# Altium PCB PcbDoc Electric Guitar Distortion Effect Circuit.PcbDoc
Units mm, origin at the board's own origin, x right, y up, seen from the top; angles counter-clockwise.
Board outline 141.4 x 38.35 mm, 2 copper layers (Top Layer, Bottom Layer), stack 1.534 mm thick; 31 components, 18 nets, 78 pads, 0 vias.
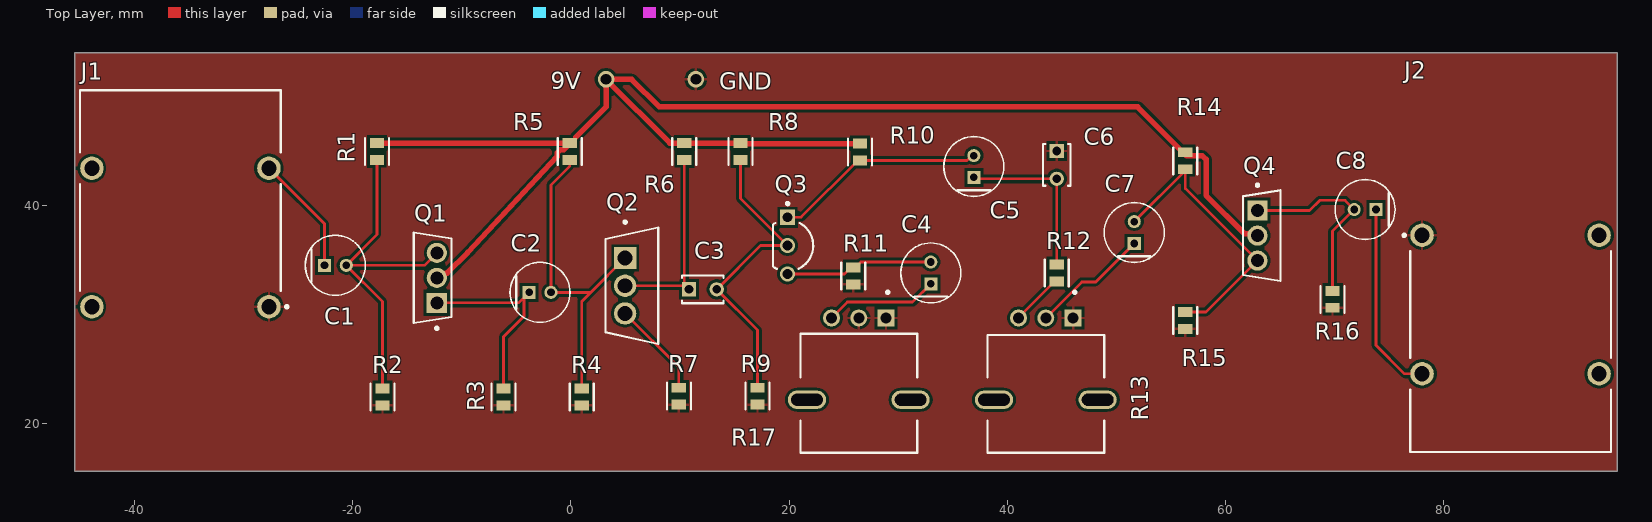
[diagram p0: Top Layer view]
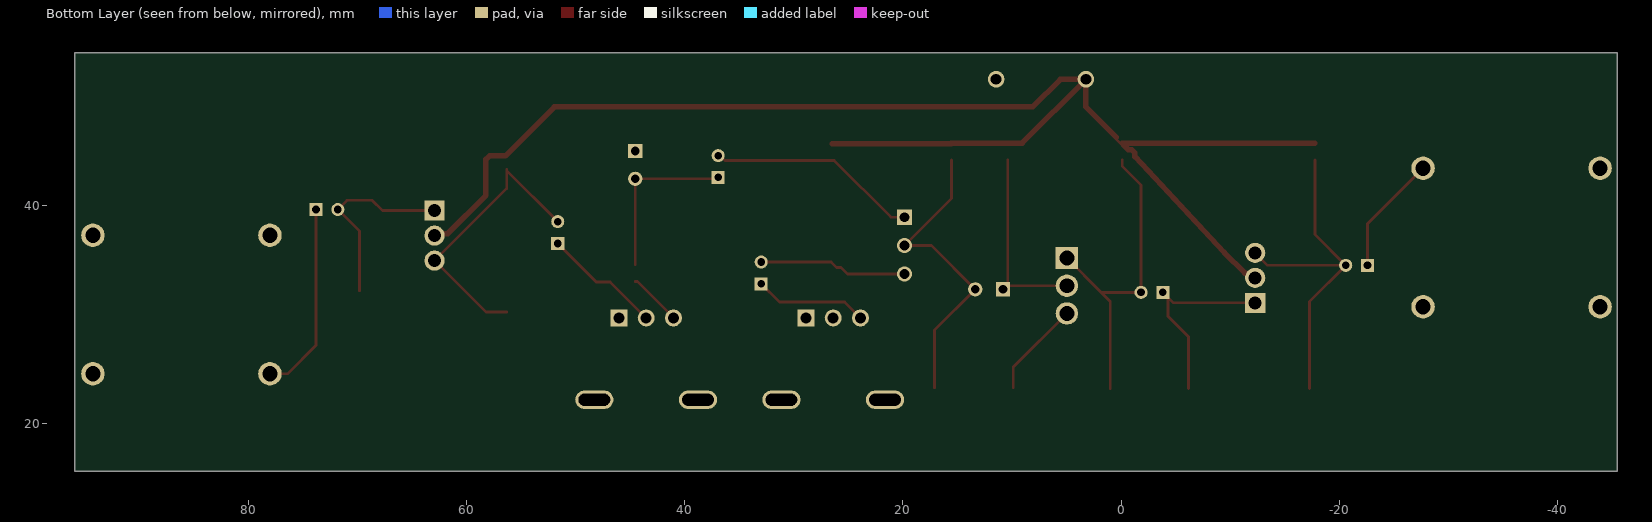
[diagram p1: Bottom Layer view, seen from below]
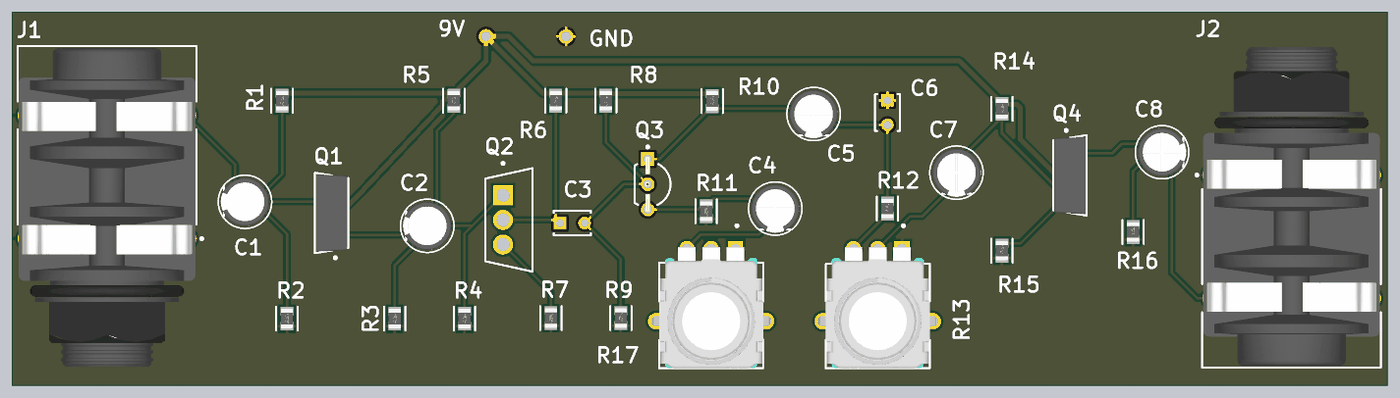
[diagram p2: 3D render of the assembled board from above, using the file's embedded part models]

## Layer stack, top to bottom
Top Solder: solder mask 0.0127, Solder Resist, Dk 3.3
Top Layer: signal copper 0.0178
Dielectric1: core 1.4986, FR-4, Dk 4.3
Bottom Layer: signal copper 0.0178
Bottom Solder: solder mask 0.0127, Solder Resist, Dk 3.3

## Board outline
-45.482,15.672 -45.482,54.026 95.917,54.026 95.917,15.672

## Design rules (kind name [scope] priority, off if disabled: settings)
Clearance [All] p1: gap=0.254 ignorepadtopadclearanceinfootprint=FALSE
DiffPairsRouting [All] p1: maxlimit=0.254 minlimit=0.254 mostfreqgap=0.254 toplayer_minwidth=0.254 toplayer_maxwidth=0.254 toplayer_prefwidth=0.254 bottomlayer_minwidth=0.254 bottomlayer_maxwidth=0.254 bottomlayer_prefwidth=0.254 maxuncoupledlength=12.7
HoleSize [All] p1: absolutevalues=TRUE maxlimit=7.62 minlimit=0.254 maxpercent=80.000 minpercent=20.000
MinimumAnnularRing [All] p1: minimumring=0.2
PasteMaskExpansion [All] p1: expansion=0.254
PlaneClearance [All] p1: clearance=0.381
PlaneConnect [All] p1: pad.planeconnectstyle=Relief pad.reliefexpansion=0.508 pad.reliefentries=4 pad.reliefconductorwidth=0.254 pad.reliefairgap=0.254 via.planeconnectstyle=Direct via.reliefexpansion=0.508 via.reliefentries=4 via.reliefconductorwidth=0.254 via.reliefairgap=0.254
PolygonConnect [All] p1: thpad.connectstyle=Relief thpad.reliefconductorwidth=0.254 thpad.reliefentries=4 thpad.polygonreliefangle="90 Angle" thpad.airgapwidth=0.254 smdpad.connectstyle=Relief smdpad.reliefconductorwidth=0.254 smdpad.reliefentries=4 smdpad.polygonreliefangle="90 Angle" smdpad.airgapwidth=0.254 via.connectstyle=Direct via.reliefconductorwidth=0.254 via.reliefentries=4 via.polygonreliefangle="90 Angle" via.airgapwidth=0.254
RoutingVias [All] p1: holewidth=0.254 width=0.508 viastyle="Through Hole" minholewidth=0.254 minwidth=0.508 maxholewidth=0.254 maxwidth=0.508
SMDNeckDown [All] p1: percent=100.000
SilkToSolderMaskClearance SilkscreenOverComponentPads [IsPad] p1: minsilkscreentomaskgap=0.254 clearancetoexposedcopper=TRUE
SolderMaskExpansion [All] p1: expansion=0.254 istentingtop=FALSE
SupplyNets "Schematic Supply Nets_1" [InNet('9V')] p1: voltage=0.000
SupplyNets "Schematic Supply Nets" [InNet('GND')] p2: voltage=0.000
Width [All] p1: maxlimit=1 minlimit=0.254 preferedwidth=0.254 bottomlayer_maxwidth=0.254 minimp=50.000000 maximp=50.000000 favimp=50.000000
24 further rules are at their usual default settings.

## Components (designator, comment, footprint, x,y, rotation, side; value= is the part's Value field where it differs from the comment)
C1 "1uF" FP-RAD-TH-D_5_0_5-L_11_1-MFG -21.587,34.535 r0 top
C2 "1uF" FP-RAD-TH-D_5_0_5-L_11_1-MFG -2.827,32.055 r0 top
C3 "10nF" KEMT-C315-THT-2 12.098,32.335 r0 top
C4 "10uF" FP-RAD-TH-D_5_0_5-L_11_1-MFG 32.991,33.838 r90 top
C5 "1uF" FP-RAD-TH-D_5_0_5-L_11_1-MFG 36.935,43.592 r90 top
C6 "10nF" KEMT-C315-THT-2 44.535,43.737 r270 top
C7 "1uF" FP-RAD-TH-D_5_0_5-L_11_1-MFG 51.638,37.541 r90 top
C8 "4.7uF" FP-RAD-TH-D_5_0_5-L_11_1-MFG 72.796,39.649 r180 top
J1 "NMJ4HFD2" FP-NMJ4HFD2-MFG -35.789,33.96 r270 top
J2 "NMJ4HFD2" FP-NMJ4HFD2-MFG 86.131,34.061 r90 top
Q1 "BD175" FP-340AS-MFG -12.675,33.385 r180 top
Q2 "IRFZ44N" FP-TO-220AB-MFG 5.588,32.664 r0 top
Q3 "BC337-40RL1G" ONSC-TO-92-3-29-11_AM_BL 19.862,36.347 r270 top
Q4 "BD175" FP-340AS-MFG 63.322,37.262 r0 top
R1 "470k" FP-CRGP0805-IPC_C -17.772,44.96 r90 top value=470KΩ
R2 "470k" FP-CRGP0805-IPC_C -17.272,22.479 r90 top value=470KΩ
R3 "1K" FP-CRGP0805-IPC_C -6.177,22.479 r90 top value=470KΩ
R4 "100k" FP-CRGP0805-IPC_C 1.004,22.479 r90 top value=470KΩ
R5 "120K" FP-CRGP0805-IPC_C -0.096,44.96 r90 top value=470KΩ
R6 "15k" FP-CRGP0805-IPC_C 10.398,44.96 r90 top value=470KΩ
R7 "1K" FP-CRGP0805-IPC_C 9.898,22.538 r90 top value=470KΩ
R8 "47k" FP-CRGP0805-IPC_C 15.551,44.96 r90 top value=470KΩ
R9 "27k" FP-CRGP0805-IPC_C 17.1,22.538 r90 top value=470KΩ
R10 "6.8k" FP-CRGP0805-IPC_C 26.502,44.922 r90 top value=470KΩ
R11 "4.7k" FP-CRGP0805-IPC_C 25.877,33.564 r90 top value=470KΩ
R12 "100k" FP-CRGP0805-IPC_C 44.535,33.838 r90 top value=470KΩ
R13 "10k" FP-RK09L1140A2U-MFG 43.535,23.038 r180 top value=10kΩ
R14 "1M" FP-CRGP0805-IPC_C 56.319,44.12 r90 top value=470KΩ
R15 "1M" FP-CRGP0805-IPC_C 56.319,29.489 r90 top value=470KΩ
R16 "1K" FP-CRGP0805-IPC_C 69.819,31.42 r90 top value=470KΩ
R17 "10k" FP-RK09L1140A2U-MFG 26.391,23.038 r180 top value=10kΩ

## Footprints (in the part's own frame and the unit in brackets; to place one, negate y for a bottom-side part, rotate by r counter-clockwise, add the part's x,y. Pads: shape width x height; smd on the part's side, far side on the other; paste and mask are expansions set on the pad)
FP-340AS-MFG [mm]
  rect 1.85x1.85 hole 1.2 paste-2539.97 mask+0: 1(-0.387,2.29)
  round 1.85 hole 1.2 paste-2539.97 mask+0: 2(-0.387,0) 3(-0.387,-2.29)
  silkscreen extent -1.73,-4.15 1.73,4.75, body extent -1.83,-4.25 1.83,4.25, height 0.25
FP-CRGP0805-IPC_C [mm]
  rect 0.906x1.31 smd paste+0 mask+0: 1(-0.776,0) 2(0.776,0)
  silkscreen extent -1.23,-1.1 1.23,1.1, body extent -1.33,-0.8 1.33,0.8, height 0.25
FP-NMJ4HFD2-MFG [mm]
  round 2.15 hole 1.4 paste-2539.97 mask+0: S(3.225,8.115) SN(3.225,-8.115) T(-9.475,8.115) TN(-9.475,-8.115)
  silkscreen extent -16.63,-9.2 3.35,9.88, body extent -16.73,-9.3 16.73,9.3, height 0.25
FP-RAD-TH-D_5_0_5-L_11_1-MFG [mm]
  rect 1.2x1.2 hole 0.7 paste-2539.97 mask+0: 1(-1,0)
  round 1.2 hole 0.7 paste-2539.97 mask+0: 2(1,0)
  silkscreen extent -2.75,-2.75 2.75,2.75, body extent -2.85,-2.85 2.85,2.85, height 0.25
FP-RK09L1140A2U-MFG [mm]
  rect 1.55x1.55 hole 1 paste-2539.97 mask+0: 1(-2.5,-6.675)
  round 1.55 hole 1 paste-2539.97 mask+0: 2(0,-6.675) 3(2.5,-6.675)
  rrect100% 3.5x1.7 hole 1.1 slot 2.9 at 0 deg paste-2539.97 mask+0: 4(-4.75,0.825) 5(4.75,0.825)
  silkscreen extent -5.35,-9.15 5.35,5.68, body extent -6.6,-7.55 6.6,5.77, height 0.25
FP-TO-220AB-MFG [mm]
  rect 2.05x2.05 hole 1.35 paste-2539.97 mask+0: 1(-0.62,2.54)
  round 2.05 hole 1.35 paste-2539.97 mask+0: 2(-0.62,0) 3(-0.62,-2.54)
  silkscreen extent -2.41,-5.34 2.41,5.96
KEMT-C315-THT-2 [mm] "THD, 2-Leads, Body 3.81x2.54mm"
  rect 1.3x1.3 hole 0.8: 1(-1.27,0)
  round 1.3 hole 0.8: 2(1.27,0)
  silkscreen extent -1.91,-1.27 1.91,1.27, body extent -1.91,-1.27 1.91,1.27, height 4.66
ONSC-TO-92-3-29-11_AM_BL [mm] "TO, 3-Leads, Body Dia 4.7mm, Pitch 2.6mm"
  rect 1.4x1.4 hole 0.9: 1(-2.6,0)
  round 1.4 hole 0.9: 2(0,0) 3(2.6,0)
  silkscreen extent -3.97,-1.34 2.13,2.35, body extent -2.84,-1.34 2.84,2.35, height 5.33

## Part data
C1 C2 C5 C7: library part CMP-05427-001266-1, "Aluminum Electrolytic Capacitors (Radial Lead Type) 1uF ±20% 50V", Case/Package=Radial, Max Operating Temperature=105°C, Min Operating Temperature=-40°C, Package Quantity=2000, Ripple Current=8mA, Tolerance=20%, Voltage Rating=50V
C3 C6: library part CMP-1664-00007-1, "Capacitor, Ceramic, 0.01 uF, +/- 10%, 100 V, X7R, -55 to 125 degC, 2-Pin THD, RoHS, Bulk", Case\Package=PDIP, Forward Current="60 mA", Forward Voltage="1.5 V", Max Operating Temperature="100 degC", Max Power Dissipation="400 mW", Min Operating Temperature="-55 degC", Output Voltage="70 V", Package Quantity=2000
C4: library part CMP-05427-000246-1, "Aluminum Electrolytic Capacitors (Radial Lead Type) 10uF ±20% 50V"
C8: library part CMP-05427-000256-1, "Aluminum Electrolytic Capacitors (Radial Lead Type) AEC-Q200 Qualified 4.7uF ±20% 50V", Case/Package=Radial, ESR (Equivalent Series Resistance)=1.3R, Max Operating Temperature=105°C, Min Operating Temperature=-55°C, Package Quantity=2000, Ratings=AEC-Q200, Ripple Current=95mA, Tolerance=20%, Voltage Rating=50V
J1 J2: library part CMP-78736-000001-1, "Conn 1/4\" Mono Jack F 3 POS Solder RA Thru-Hole 3 Terminal 1 Port", Current Rating=0.5A, Manufacturer=Neutrik, Package=0, Temperature="-25°C to +70°C", Temperature Range High=+70°C, Temperature Range Low=-25°C, Voltage Rating=50V
Q1 Q4: library part CMP-013-00036-1, "npn", Case/Package=TO-126, Frequency=15MHz, Max Operating Temperature=150°C, Min Operating Temperature=-55°C
Q2: library part CMP-013-00037-1, Case/Package=TO-220AB
Q3: library part CMP-1048-01582-1, "Amplifier Transistor, NPN Silicon, 3-Pin TO-92, Pb-Free, Tape and Reel", Manufacturer="On Semiconductor"
R1 R2 R3 R4 R5 R6 R7 R8 R9 R10 R11 R12 R14 R15 R16: library part CMP-03211-007232-1, "CRGP0805 470KΩ 0.33W ±100ppm/°C 1% 150V", Ambient Temperature Range High=+70°C, Manufacturer=TE, Manufacturer Part Number=CRGP0805F470K, Package=CRGP0805, Power Rating=0.33W, Resistance=470KΩ, Temperature="-55°C to +155°C", Temperature Coefficient=±100ppm/°C, Temperature Range High=+155°C, Temperature Range Low=-55°C, Tolerance=0.01, Voltage Rating=150V
R13 R17: library part CMP-24118-000002-1, "9mm Size Metal Shaft Snap-in Type RK09L Series", Manufacturer=ALPS, Manufacturer Part Number=RK09L1140A2U, Power Rating=0.05W, Resistance=10kΩ, Temperature="-10°C to +70°C", Temperature Range High=+70°C, Temperature Range Low=-10°C, Tolerance=20%, Voltage Rating=50V

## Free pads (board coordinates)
  round 1.524 hole 1: 1(3.226,51.587) 1(11.455,51.587)

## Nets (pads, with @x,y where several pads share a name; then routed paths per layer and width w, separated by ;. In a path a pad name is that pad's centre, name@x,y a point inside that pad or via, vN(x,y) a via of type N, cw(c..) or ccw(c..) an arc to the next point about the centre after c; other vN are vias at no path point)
9V: pad.1@3.226,51.587 Q1.2 Q4.2 R1.2 R5.2 R6.2 R8.2 R10.2 R14.2 | length 136
  Top Layer w0.254: R5.2 0.105,45.736 0.431,46.062 0.431,46.264 ; R8.2 R8.2@15.59,45.698
  Top Layer w0.5: R1.2 -0.286,45.736 R5.2 -0.286,45.533 -0.51,45.294 -0.662,45.141 -0.96,45.141 -1.255,44.846 -1.255,44.495 -9.437,35.73 -9.449,35.718 -11.35,33.816 -11.491,33.816 -11.922,33.385 Q1.2 ; 0.431,46.264 3.226,49.059 pad.1@3.226,51.587 ; R8.2 R6.2 9.077,45.736 pad.1@3.226,51.587 ; R8.2@15.59,45.698 R10.2 ; Q4.2 62.768,37.429 61.733,37.429 58.228,40.934 58.228,44.237 57.895,44.57 56.443,44.57 51.955,49.059 8.103,49.059 5.574,51.587 pad.1@3.226,51.587
GND: C6.1 J1.S J2.S pad.1@11.455,51.587 R2.1 R3.1 R4.1 R7.1 R9.1 R11.1 R13.1 R15.1 R16.1 R17.1 R17.2
NetC1_1: C1.1 J1.T | length 11
  Top Layer w0.254: J1.T -22.587,38.349 C1.1
NetC1_2: C1.2 Q1.3 R1.1 R2.2 | length 32.2
  Top Layer w0.254: R1.1 -17.772,37.351 C1.2 ; R2.2 -17.272,31.22 C1.2 ; Q1.3 -13.427,34.535 C1.2
NetC2_1: C2.1 Q1.1 R3.2 | length 18.6
  Top Layer w0.254: Q1.1 -4.788,31.095 C2.1 -4.3,31.582 -4.3,29.863 -6.177,27.986 R3.2
NetC2_2: C2.2 Q2.1 R4.2 R5.1 | length 30.1
  Top Layer w0.254: R5.1 -0.096,43.631 -1.827,41.9 C2.2 1.818,32.055 ; R4.2 1.004,31.24 1.818,32.055 ; Q2.1 1.818,32.055
NetC3_1: C3.1 Q2.2 R6.1 | length 18
  Top Layer w0.254: Q2.2 10.498,32.664 C3.1 10.398,32.765 R6.1
NetC3_2: C3.2 Q3.2 R8.1 R9.2 | length 28.3
  Top Layer w0.254: R8.1 15.551,40.658 Q3.2 17.381,36.347 C3.2 17.1,28.602 R9.2
NetC4_1: C4.1 R17.3 | length 10.4
  Top Layer w0.254: R17.3 25.341,31.163 31.315,31.163 C4.1
NetC4_2: C4.2 Q3.3 R11.2 | length 13.6
  Top Layer w0.254: Q3.3 25.083,33.747 25.676,34.34 R11.2 26.079,34.34 26.578,34.838 C4.2
NetC5_1: C5.1 C6.2 R12.2 | length 15.5
  Top Layer w0.254: C5.1 37.061,42.467 C6.2 R12.2
NetC5_2: C5.2 Q3.1 R10.1 | length 19.4
  Top Layer w0.254: Q3.1 21.102,38.947 26.301,44.145 36.313,44.145 36.76,44.592 C5.2
NetC7_1: C7.1 R13.2 | length 10.9
  Top Layer w0.254: R13.2 46.837,33.014 48.111,33.014 C7.1
NetC7_2: C7.2 Q4.3 R14.1 R15.2 | length 26.4
  Top Layer w0.254: C7.2 56.319,43.222 R14.1 56.319,41.587 Q4.3 58.228,30.265 R15.2
NetC8_1: C8.1 J2.T | length 17.7
  Top Layer w0.254: C8.1 73.796,27.211 76.421,24.586 J2.T
NetC8_2: C8.2 Q4.1 R16.2 | length 17.9
  Top Layer w0.254: Q4.1 67.703,39.552 68.644,40.493 70.953,40.493 C8.2 69.819,37.672 R16.2
NetQ2_3: Q2.3 R7.2 | length 8.9
  Top Layer w0.254: Q2.3 9.898,25.195 R7.2
NetR12_1: R12.1 R13.3 | length 4.9
  Top Layer w0.254: R13.3 41.035,29.764 44.333,33.062 R12.1
pads on no net: J1.SN J1.TN J2.SN J2.TN R13.4 R13.5 R17.4 R17.5

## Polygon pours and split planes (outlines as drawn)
GND on Top Layer "GND_L01_P000" (solid, pour order 0): -45.482,54.026 -45.482,15.672 95.917,15.672 95.917,54.026 -45.482,54.026

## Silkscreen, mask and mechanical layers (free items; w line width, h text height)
Top Overlay:
  text "9V" at -1.827,50.685 h1.52
  text "GND" at 13.622,50.65 h1.52
Board:
  the board outline again, w0.254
